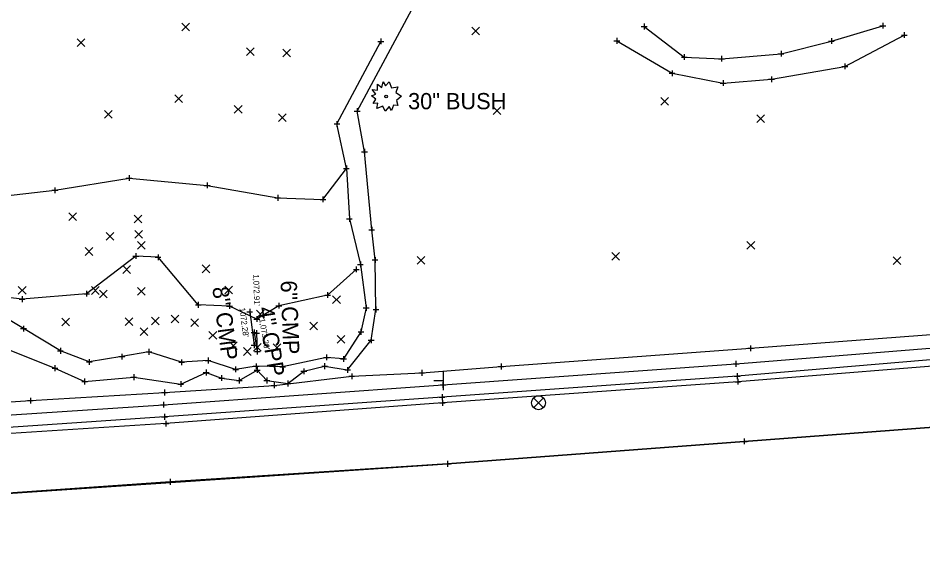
# Model space of a CAD drawing. Extents: x 203564 to 204038, y 344976 to 345157.
# Drawn here: x 203796.6 to 203952.6, y 344976.5 to 345067.2 of the extents above; entities that cross this region are included whole.
import ezdxf

# ---------------------------------------------------------------- set-up
doc = ezdxf.new("R2010")
doc.units = 0
for name, color, linetype in [('_CIVIL_CONSTRUCTION', 7, 'Continuous'), ('BM_P_Point', 7, 'Continuous'), ('DR_X_Storm_Sewer', 7, 'Continuous'), ('DR_X_Text', 7, 'Continuous'), ('PM_X_Channelizing_Line', 7, 'Continuous'), ('RW_X_CL', 7, 'Continuous'), ('RW_X_CL_100_Bearings', 7, 'Continuous'), ('RW_X_CL_100_Cardinal_Points', 7, 'Continuous'), ('RW_X_CL_100_Curve_Data', 7, 'Continuous'), ('RW_X_CL_100_Distances', 7, 'Continuous'), ('RW_X_CL_100_Stations', 7, 'Continuous'), ('RW_X_Esmt_LA', 7, 'Continuous'), ('SC_Scratch1', 7, 'Continuous'), ('SV_P_Control_Cells_Set', 7, 'Continuous'), ('SV_X_Break_Lines', 7, 'Continuous'), ('SV_X_Edge_of_Slip', 7, 'Continuous'), ('SV_X_Terrain_Boundary', 7, 'Continuous'), ('VG_X_Text', 7, 'Continuous')]:
    doc.layers.add(name, color=color, linetype=linetype)

msp = doc.modelspace()

# ---------------------------------------------------------------- linework, layer by layer
at = {"layer": '_CIVIL_CONSTRUCTION'}
for p, q in [((203904.05, 345065.76), (203905.05, 345065.76)), ((203904.55, 345066.26), (203904.55, 345065.26)), ((203904.55, 345065.76), (203904.55, 345065.76)), ((203945.2, 345065.9), (203946.2, 345065.9)), ((203945.7, 345066.4), (203945.7, 345065.4)), ((203945.7, 345065.9), (203945.7, 345065.9)), ((203859.15, 345063.7), (203859.15, 345062.7)), ((203899.85, 345063.78), (203899.85, 345062.78)), ((203936.83, 345063.76), (203936.83, 345062.76)), ((203948.91, 345064.29), (203949.91, 345064.29)), ((203949.41, 345064.79), (203949.41, 345063.79)), ((203949.41, 345064.29), (203949.41, 345064.29)), ((203858.65, 345063.2), (203859.65, 345063.2)), ((203859.15, 345063.2), (203859.15, 345063.2)), ((203899.35, 345063.28), (203900.35, 345063.28)), ((203899.85, 345063.28), (203899.85, 345063.28)), ((203936.33, 345063.26), (203937.33, 345063.26)), ((203936.83, 345063.26), (203936.83, 345063.26)), ((203910.97, 345060.49), (203911.97, 345060.49)), ((203911.47, 345060.99), (203911.47, 345059.99)), ((203911.47, 345060.49), (203911.47, 345060.49)), ((203917.39, 345060.2), (203918.39, 345060.2)), ((203917.89, 345060.7), (203917.89, 345059.7)), ((203917.89, 345060.2), (203917.89, 345060.2)), ((203927.65, 345061.07), (203928.65, 345061.07)), ((203928.15, 345061.57), (203928.15, 345060.57)), ((203928.15, 345061.07), (203928.15, 345061.07)), ((203938.65, 345058.89), (203939.65, 345058.89)), ((203939.15, 345059.39), (203939.15, 345058.39)), ((203939.15, 345058.89), (203939.15, 345058.89)), ((203908.87, 345057.69), (203909.87, 345057.69)), ((203909.37, 345058.19), (203909.37, 345057.19)), ((203909.37, 345057.69), (203909.37, 345057.69)), ((203926.51, 345057.16), (203926.51, 345056.16)), ((203917.66, 345056.01), (203918.66, 345056.01)), ((203918.16, 345056.51), (203918.16, 345055.51)), ((203918.16, 345056.01), (203918.16, 345056.01)), ((203926.01, 345056.66), (203927.01, 345056.66)), ((203926.51, 345056.66), (203926.51, 345056.66)), ((203854.59, 345051.18), (203855.59, 345051.18)), ((203855.09, 345051.68), (203855.09, 345050.68)), ((203855.09, 345051.18), (203855.09, 345051.18)), ((203851.59, 345049.45), (203851.59, 345048.45)), ((203851.09, 345048.95), (203852.09, 345048.95)), ((203851.59, 345048.95), (203851.59, 345048.95)), ((203856.34, 345044.65), (203856.34, 345043.65)), ((203855.84, 345044.15), (203856.84, 345044.15)), ((203856.34, 345044.15), (203856.34, 345044.15)), ((203853.22, 345041.8), (203853.22, 345040.8)), ((203815.75, 345040.12), (203815.75, 345039.12)), ((203852.72, 345041.3), (203853.72, 345041.3)), ((203853.22, 345041.3), (203853.22, 345041.3)), ((203815.25, 345039.62), (203816.25, 345039.62)), ((203815.75, 345039.62), (203815.75, 345039.62)), ((203828.72, 345038.37), (203829.72, 345038.37)), ((203829.22, 345038.87), (203829.22, 345037.87)), ((203829.22, 345038.37), (203829.22, 345038.37)), ((203802.46, 345037.51), (203803.46, 345037.51)), ((203802.96, 345038.01), (203802.96, 345037.01)), ((203802.96, 345037.51), (203802.96, 345037.51)), ((203840.88, 345036.21), (203841.88, 345036.21)), ((203841.38, 345036.71), (203841.38, 345035.71)), ((203841.38, 345036.21), (203841.38, 345036.21)), ((203848.68, 345035.95), (203849.68, 345035.95)), ((203849.18, 345036.45), (203849.18, 345035.45)), ((203849.18, 345035.95), (203849.18, 345035.95)), ((203853.24, 345032.59), (203854.24, 345032.59)), ((203853.74, 345033.09), (203853.74, 345032.09)), ((203853.74, 345032.59), (203853.74, 345032.59)), ((203857.09, 345030.7), (203858.09, 345030.7)), ((203857.59, 345031.2), (203857.59, 345030.2)), ((203857.59, 345030.7), (203857.59, 345030.7)), ((203816.43, 345026.17), (203817.43, 345026.17)), ((203816.93, 345026.67), (203816.93, 345025.67)), ((203816.93, 345026.17), (203816.93, 345026.17)), ((203820.26, 345025.96), (203821.26, 345025.96)), ((203820.76, 345026.46), (203820.76, 345025.46)), ((203820.76, 345025.96), (203820.76, 345025.96)), ((203858.17, 345026.01), (203858.17, 345025.01)), ((203854.93, 345024.38), (203854.93, 345023.38)), ((203855.14, 345024.74), (203856.14, 345024.74)), ((203855.64, 345025.24), (203855.64, 345024.24)), ((203855.64, 345024.74), (203855.64, 345024.74)), ((203857.67, 345025.51), (203858.67, 345025.51)), ((203858.17, 345025.51), (203858.17, 345025.51)), ((203854.43, 345023.88), (203855.43, 345023.88)), ((203854.93, 345023.88), (203854.93, 345023.88)), ((203807.94, 345019.69), (203808.94, 345019.69)), ((203808.44, 345020.19), (203808.44, 345019.19)), ((203808.44, 345019.69), (203808.44, 345019.69)), ((203849.99, 345019.96), (203849.99, 345018.96)), ((203796.81, 345018.74), (203797.81, 345018.74)), ((203797.31, 345019.24), (203797.31, 345018.24)), ((203797.31, 345018.74), (203797.31, 345018.74)), ((203827.69, 345018.26), (203827.69, 345017.26)), ((203833.07, 345018.06), (203833.07, 345017.06)), ((203841.57, 345018.12), (203841.57, 345017.12)), ((203849.49, 345019.46), (203850.49, 345019.46)), ((203849.99, 345019.46), (203849.99, 345019.46)), ((203827.19, 345017.76), (203828.19, 345017.76)), ((203827.69, 345017.76), (203827.69, 345017.76)), ((203832.57, 345017.56), (203833.57, 345017.56)), ((203833.07, 345017.56), (203833.07, 345017.56)), ((203841.07, 345017.62), (203842.07, 345017.62)), ((203841.57, 345017.62), (203841.57, 345017.62)), ((203856.12, 345017.23), (203857.12, 345017.23)), ((203856.62, 345017.73), (203856.62, 345016.73)), ((203856.62, 345017.23), (203856.62, 345017.23)), ((203857.82, 345016.96), (203858.82, 345016.96)), ((203858.32, 345017.46), (203858.32, 345016.46)), ((203858.32, 345016.96), (203858.32, 345016.96)), ((203837.28, 345015.31), (203838.28, 345015.31)), ((203837.78, 345015.81), (203837.78, 345014.81)), ((203837.78, 345015.31), (203837.78, 345015.31)), ((203797.05, 345013.67), (203798.05, 345013.67)), ((203797.55, 345014.17), (203797.55, 345013.17)), ((203797.55, 345013.67), (203797.55, 345013.67)), ((203855.73, 345013.61), (203855.73, 345012.61)), ((203855.23, 345013.11), (203856.23, 345013.11)), ((203855.73, 345013.11), (203855.73, 345013.11)), ((203857.49, 345012.16), (203857.49, 345011.16)), ((203803.92, 345010.34), (203803.92, 345009.34)), ((203856.99, 345011.66), (203857.99, 345011.66)), ((203857.49, 345011.66), (203857.49, 345011.66)), ((203922.41, 345010.28), (203923.41, 345010.28)), ((203922.91, 345010.78), (203922.91, 345009.78)), ((203922.91, 345010.28), (203922.91, 345010.28)), ((203803.42, 345009.84), (203804.42, 345009.84)), ((203803.92, 345009.84), (203803.92, 345009.84)), ((203814, 345008.83), (203815, 345008.83)), ((203814.5, 345009.33), (203814.5, 345008.33)), ((203814.5, 345008.83), (203814.5, 345008.83)), ((203818.69, 345009.65), (203819.69, 345009.65)), ((203819.19, 345010.15), (203819.19, 345009.15)), ((203819.19, 345009.65), (203819.19, 345009.65)), ((203849.29, 345008.7), (203850.29, 345008.7)), ((203849.79, 345009.2), (203849.79, 345008.2)), ((203849.79, 345008.7), (203849.79, 345008.7)), ((203852.72, 345008.94), (203852.72, 345007.94)), ((203802.98, 345007.35), (203802.98, 345006.35)), ((203808.39, 345007.92), (203809.39, 345007.92)), ((203808.89, 345008.42), (203808.89, 345007.42)), ((203808.89, 345007.92), (203808.89, 345007.92)), ((203824.31, 345007.86), (203825.31, 345007.86)), ((203824.81, 345008.36), (203824.81, 345007.36)), ((203824.81, 345007.86), (203824.81, 345007.86)), ((203828.88, 345008.16), (203829.88, 345008.16)), ((203829.38, 345008.66), (203829.38, 345007.66)), ((203829.38, 345008.16), (203829.38, 345008.16)), ((203837.17, 345007.17), (203838.17, 345007.17)), ((203837.67, 345007.67), (203837.67, 345006.67)), ((203837.67, 345007.17), (203837.67, 345007.17)), ((203842.23, 345007.56), (203842.23, 345006.56)), ((203848.96, 345007.18), (203849.96, 345007.18)), ((203849.46, 345007.68), (203849.46, 345006.68)), ((203849.46, 345007.18), (203849.46, 345007.18)), ((203852.22, 345008.44), (203853.22, 345008.44)), ((203852.72, 345008.44), (203852.72, 345008.44)), ((203879.89, 345007.63), (203879.89, 345006.63)), ((203919.88, 345007.59), (203920.88, 345007.59)), ((203920.38, 345008.09), (203920.38, 345007.09)), ((203920.38, 345007.59), (203920.38, 345007.59)), ((203802.48, 345006.85), (203803.48, 345006.85)), ((203802.98, 345006.85), (203802.98, 345006.85)), ((203816.55, 345005.8), (203816.55, 345004.8)), ((203828.54, 345006.1), (203829.54, 345006.1)), ((203829.04, 345006.6), (203829.04, 345005.6)), ((203829.04, 345006.1), (203829.04, 345006.1)), ((203831.71, 345005.64), (203831.71, 345004.64)), ((203833.62, 345006.64), (203834.62, 345006.64)), ((203834.12, 345007.14), (203834.12, 345006.14)), ((203834.12, 345006.64), (203834.12, 345006.64)), ((203837.35, 345006.51), (203838.35, 345006.51)), ((203837.85, 345007.01), (203837.85, 345006.01)), ((203837.85, 345006.51), (203837.85, 345006.51)), ((203841.73, 345007.06), (203842.73, 345007.06)), ((203842.23, 345007.06), (203842.23, 345007.06)), ((203845.39, 345006.3), (203846.39, 345006.3)), ((203845.89, 345006.8), (203845.89, 345005.8)), ((203845.89, 345006.3), (203845.89, 345006.3)), ((203852.93, 345006.53), (203853.93, 345006.53)), ((203853.43, 345007.03), (203853.43, 345006.03)), ((203853.43, 345006.53), (203853.43, 345006.53)), ((203854.14, 345005.95), (203854.14, 345004.95)), ((203865.71, 345006.03), (203866.71, 345006.03)), ((203866.21, 345006.53), (203866.21, 345005.53)), ((203866.21, 345006.03), (203866.21, 345006.03)), ((203879.39, 345007.13), (203880.39, 345007.13)), ((203879.89, 345007.13), (203879.89, 345007.13)), ((203920.59, 345005.96), (203920.59, 345004.96)), ((203807.6, 345004.55), (203808.6, 345004.55)), ((203808.1, 345005.05), (203808.1, 345004.05)), ((203808.1, 345004.55), (203808.1, 345004.55)), ((203816.05, 345005.3), (203817.05, 345005.3)), ((203816.55, 345005.3), (203816.55, 345005.3)), ((203824.16, 345004.1), (203825.16, 345004.1)), ((203824.66, 345004.6), (203824.66, 345003.6)), ((203824.66, 345004.1), (203824.66, 345004.1)), ((203831.21, 345005.14), (203832.21, 345005.14)), ((203831.71, 345005.14), (203831.71, 345005.14)), ((203834.26, 345004.72), (203835.26, 345004.72)), ((203834.76, 345005.22), (203834.76, 345004.22)), ((203834.76, 345004.72), (203834.76, 345004.72)), ((203839, 345004.71), (203840, 345004.71)), ((203839.5, 345005.21), (203839.5, 345004.21)), ((203839.5, 345004.71), (203839.5, 345004.71)), ((203840.75, 345004.38), (203840.75, 345003.38)), ((203842.62, 345004.19), (203843.62, 345004.19)), ((203843.12, 345004.69), (203843.12, 345003.69)), ((203843.12, 345004.19), (203843.12, 345004.19)), ((203853.64, 345005.45), (203854.64, 345005.45)), ((203854.14, 345005.45), (203854.14, 345005.45)), ((203869.87, 345004.45), (203869.87, 345003.45)), ((203920.09, 345005.46), (203921.09, 345005.46)), ((203920.19, 345004.51), (203921.19, 345004.51)), ((203920.59, 345005.46), (203920.59, 345005.46)), ((203920.69, 345005.01), (203920.69, 345004.01)), ((203920.69, 345004.51), (203920.69, 345004.51)), ((203821.37, 345002.65), (203822.37, 345002.65)), ((203821.87, 345003.15), (203821.87, 345002.15)), ((203821.87, 345002.65), (203821.87, 345002.65)), ((203840.25, 345003.88), (203841.25, 345003.88)), ((203840.75, 345003.88), (203840.75, 345003.88)), ((203869.37, 345003.95), (203870.37, 345003.95)), ((203869.87, 345003.95), (203869.87, 345003.95)), ((203798.25, 345001.25), (203799.25, 345001.25)), ((203798.75, 345001.75), (203798.75, 345000.75)), ((203798.75, 345001.25), (203798.75, 345001.25)), ((203821.68, 345001.04), (203821.68, 345000.04)), ((203869.22, 345001.85), (203870.22, 345001.85)), ((203869.72, 345002.35), (203869.72, 345001.35)), ((203869.72, 345001.85), (203869.72, 345001.85)), ((203869.77, 345001.34), (203869.77, 345000.34)), ((203821.18, 345000.54), (203822.18, 345000.54)), ((203821.68, 345000.54), (203821.68, 345000.54)), ((203869.27, 345000.84), (203870.27, 345000.84)), ((203869.77, 345000.84), (203869.77, 345000.84)), ((203821.37, 344998.44), (203822.37, 344998.44)), ((203821.87, 344998.94), (203821.87, 344997.94)), ((203821.87, 344998.44), (203821.87, 344998.44)), ((203821.61, 344997.28), (203822.61, 344997.28)), ((203822.11, 344997.78), (203822.11, 344996.78)), ((203822.11, 344997.28), (203822.11, 344997.28)), ((203921.82, 344994.71), (203921.82, 344993.71)), ((203921.82, 344994.71), (203921.82, 344993.71)), ((203921.32, 344994.21), (203922.32, 344994.21)), ((203921.32, 344994.21), (203922.32, 344994.21)), ((203921.82, 344994.21), (203921.82, 344994.21)), ((203921.82, 344994.21), (203921.82, 344994.21)), ((203870.16, 344990.35), (203871.16, 344990.35)), ((203870.16, 344990.35), (203871.16, 344990.35)), ((203870.66, 344990.85), (203870.66, 344989.85)), ((203870.66, 344990.85), (203870.66, 344989.85)), ((203870.66, 344990.35), (203870.66, 344990.35)), ((203870.66, 344990.35), (203870.66, 344990.35)), ((203822.32, 344987.23), (203823.32, 344987.23)), ((203822.32, 344987.23), (203823.32, 344987.23)), ((203822.82, 344987.73), (203822.82, 344986.73)), ((203822.82, 344987.73), (203822.82, 344986.73)), ((203822.82, 344987.23), (203822.82, 344987.23)), ((203822.82, 344987.23), (203822.82, 344987.23))]:
    msp.add_line(p, q, dxfattribs=at)
at = {"layer": 'BM_P_Point'}
for p, q in [((203887.18, 345000.03), (203885.49, 345001.73)), ((203885.49, 345000.03), (203887.18, 345001.73))]:
    msp.add_line(p, q, dxfattribs=at)
msp.add_circle((203886.33, 345000.88), 1.2, dxfattribs=at)
at = {"layer": 'DR_X_Storm_Sewer'}
for p, q in [((203836.55, 345016.57), (203837.3, 345010.82)), ((203837.33, 345012.99), (203837.86, 345009.7)), ((203837.74, 345012.9), (203837.86, 345009.7))]:
    msp.add_line(p, q, dxfattribs=at)
at = {"layer": 'PM_X_Channelizing_Line'}
msp.add_lwpolyline([(203965.84, 344997.53), (203921.82, 344994.21), (203870.66, 344990.35), (203822.82, 344987.23), (203774.29, 344983.85), (203725.72, 344980.7), (203661.3, 344976.54)], dxfattribs=at)
at = {"layer": 'RW_X_CL'}
for p, q in [((203869.91, 345006.24), (203869.91, 345003.04)), ((203869.91, 345004.64), (203868.31, 345004.64)), ((203869.91, 345004.64), (203869.91, 345004.64))]:
    msp.add_line(p, q, dxfattribs=at)
at = {"layer": 'RW_X_CL_100_Bearings'}
for p, q in [((203824.84, 345065.01), (203826.17, 345066.35)), ((203824.84, 345066.35), (203826.17, 345065.01)), ((203874.85, 345064.3), (203876.18, 345065.63)), ((203874.85, 345065.63), (203876.18, 345064.3)), ((203806.82, 345062.3), (203808.15, 345063.63)), ((203806.82, 345063.63), (203808.15, 345062.3)), ((203835.98, 345060.77), (203837.31, 345062.11)), ((203835.98, 345062.11), (203837.31, 345060.77)), ((203842.25, 345060.54), (203843.58, 345061.88)), ((203842.25, 345061.88), (203843.58, 345060.54)), ((203823.62, 345052.63), (203824.95, 345053.97)), ((203823.62, 345053.97), (203824.95, 345052.63)), ((203907.44, 345052.2), (203908.77, 345053.54)), ((203907.44, 345053.54), (203908.77, 345052.2)), ((203811.51, 345049.93), (203812.85, 345051.26)), ((203811.51, 345051.26), (203812.85, 345049.93)), ((203833.9, 345050.79), (203835.23, 345052.13)), ((203833.9, 345052.13), (203835.23, 345050.79)), ((203878.51, 345050.58), (203879.85, 345051.92)), ((203878.51, 345051.92), (203879.85, 345050.58)), ((203841.52, 345049.37), (203842.85, 345050.7)), ((203841.52, 345050.7), (203842.85, 345049.37)), ((203923.99, 345049.19), (203925.33, 345050.53)), ((203923.99, 345050.53), (203925.33, 345049.19)), ((203805.35, 345032.28), (203806.68, 345033.61)), ((203805.35, 345033.61), (203806.68, 345032.28)), ((203816.62, 345031.91), (203817.96, 345033.25)), ((203816.62, 345033.25), (203817.96, 345031.91)), ((203816.73, 345029.27), (203818.06, 345030.6)), ((203816.73, 345030.6), (203818.06, 345029.27)), ((203811.8, 345028.9), (203813.13, 345030.23)), ((203811.8, 345030.23), (203813.13, 345028.9)), ((203808.18, 345026.29), (203809.51, 345027.63)), ((203808.18, 345027.63), (203809.51, 345026.29)), ((203817.19, 345027.36), (203818.52, 345028.7)), ((203817.19, 345028.7), (203818.52, 345027.36)), ((203922.28, 345027.36), (203923.61, 345028.7)), ((203922.28, 345028.7), (203923.61, 345027.36)), ((203865.43, 345024.78), (203866.77, 345026.12)), ((203865.43, 345026.12), (203866.77, 345024.78)), ((203898.99, 345025.45), (203900.32, 345026.78)), ((203898.99, 345026.78), (203900.32, 345025.45)), ((203947.5, 345024.72), (203948.83, 345026.06)), ((203947.5, 345026.06), (203948.83, 345024.72)), ((203814.7, 345023.18), (203816.03, 345024.52)), ((203814.7, 345024.52), (203816.03, 345023.18)), ((203828.34, 345023.3), (203829.67, 345024.64)), ((203828.34, 345024.64), (203829.67, 345023.3)), ((203796.65, 345019.59), (203797.99, 345020.93)), ((203796.65, 345020.93), (203797.99, 345019.59)), ((203809.25, 345019.56), (203810.58, 345020.9)), ((203809.25, 345020.9), (203810.58, 345019.56)), ((203810.64, 345018.97), (203811.97, 345020.3)), ((203810.64, 345020.3), (203811.97, 345018.97)), ((203817.2, 345019.44), (203818.53, 345020.78)), ((203817.2, 345020.78), (203818.53, 345019.44)), ((203832.27, 345019.64), (203833.6, 345020.98)), ((203832.27, 345020.98), (203833.6, 345019.64)), ((203850.84, 345017.99), (203852.18, 345019.33)), ((203850.84, 345019.33), (203852.18, 345017.99)), ((203837.73, 345015.49), (203839.06, 345016.83)), ((203837.73, 345016.83), (203839.06, 345015.49)), ((203804.15, 345014.15), (203805.49, 345015.49)), ((203804.15, 345015.49), (203805.49, 345014.15)), ((203815.06, 345014.2), (203816.39, 345015.54)), ((203815.06, 345015.54), (203816.39, 345014.2)), ((203819.64, 345014.31), (203820.97, 345015.65)), ((203819.64, 345015.65), (203820.97, 345014.31)), ((203823.02, 345014.67), (203824.36, 345016.01)), ((203823.02, 345016.01), (203824.36, 345014.67)), ((203826.41, 345014.03), (203827.74, 345015.36)), ((203826.41, 345015.36), (203827.74, 345014.03)), ((203817.66, 345012.46), (203819, 345013.8)), ((203817.66, 345013.8), (203819, 345012.46)), ((203846.9, 345013.46), (203848.24, 345014.79)), ((203846.9, 345014.79), (203848.24, 345013.46)), ((203829.53, 345011.82), (203830.86, 345013.15)), ((203829.53, 345013.15), (203830.86, 345011.82)), ((203851.63, 345011.17), (203852.96, 345012.5)), ((203851.63, 345012.5), (203852.96, 345011.17)), ((203833.05, 345010.07), (203834.38, 345011.41)), ((203833.05, 345011.41), (203834.38, 345010.07)), ((203835.49, 345009.05), (203836.82, 345010.38)), ((203835.49, 345010.38), (203836.82, 345009.05)), ((203837.19, 345009.75), (203838.52, 345011.08)), ((203837.19, 345011.08), (203838.52, 345009.75)), ((203840.6, 345009.72), (203841.93, 345011.06)), ((203840.6, 345011.06), (203841.93, 345009.72))]:
    msp.add_line(p, q, dxfattribs=at)
at = {"layer": 'RW_X_CL_100_Cardinal_Points'}
msp.add_lwpolyline([(203859.98, 345055.51), (203860.58, 345056.24), (203861, 345055.19), (203862.09, 345055.37), (203861.75, 345054.36), (203862.7, 345053.76), (203861.84, 345053.03), (203862.09, 345052.12), (203861.34, 345052.18), (203861.01, 345051.27), (203860.58, 345051.96), (203859.91, 345051.15), (203859.48, 345052.03), (203858.46, 345051.6), (203858.65, 345052.54), (203857.84, 345052.46), (203858.31, 345053.25), (203857.54, 345053.82), (203858.28, 345054.08), (203857.67, 345054.89), (203858.61, 345054.78), (203858.58, 345055.81), (203859.33, 345055.25), (203859.54, 345056.23), (203859.98, 345055.51)], dxfattribs=at)
msp.add_circle((203860.06, 345053.7), 0.23, dxfattribs=at)
at = {"layer": 'RW_X_CL_100_Curve_Data'}
for p, q in [((203836.05, 345016.57), (203837.05, 345016.57)), ((203836.55, 345017.07), (203836.55, 345016.07)), ((203836.55, 345016.57), (203836.55, 345016.57)), ((203837.33, 345013.49), (203837.33, 345012.49)), ((203837.74, 345013.4), (203837.74, 345012.4)), ((203836.83, 345012.99), (203837.83, 345012.99)), ((203837.24, 345012.9), (203838.24, 345012.9)), ((203837.33, 345012.99), (203837.33, 345012.99)), ((203837.74, 345012.9), (203837.74, 345012.9)), ((203836.8, 345010.82), (203837.8, 345010.82)), ((203837.3, 345011.32), (203837.3, 345010.32)), ((203837.3, 345010.82), (203837.3, 345010.82)), ((203837.36, 345009.7), (203838.36, 345009.7)), ((203837.86, 345010.2), (203837.86, 345009.2)), ((203837.86, 345009.7), (203837.86, 345009.7))]:
    msp.add_line(p, q, dxfattribs=at)
at = {"layer": 'RW_X_CL_100_Distances'}
msp.add_lwpolyline([(203964.79, 345009.21), (203920.59, 345005.46), (203869.72, 345001.85), (203821.87, 344998.44), (203773.9, 344995.18), (203724.14, 344991.94), (203661.21, 344987.77)], dxfattribs=at)
at = {"layer": 'RW_X_CL_100_Stations'}
msp.add_lwpolyline([(203660.93, 344989.96), (203723.73, 344994.26), (203773.58, 344997.37), (203821.68, 345000.54), (203869.87, 345003.95), (203920.38, 345007.59), (203965.26, 345011.21)], dxfattribs=at)
at = {"layer": 'RW_X_Esmt_LA'}
msp.add_lwpolyline([(203965.84, 344997.53), (203921.82, 344994.21), (203870.66, 344990.35), (203822.82, 344987.23), (203774.29, 344983.85), (203725.72, 344980.7), (203661.3, 344976.54)], dxfattribs=at)
at = {"layer": 'SV_P_Control_Cells_Set'}
msp.add_lwpolyline([(203965, 345008.04), (203920.69, 345004.51), (203869.77, 345000.84), (203822.11, 344997.28), (203773.93, 344994.18), (203724.2, 344990.95), (203660.85, 344986.88)], dxfattribs=at)
at = {"layer": 'SV_X_Break_Lines'}
for points in [[(203765.03, 345042.4), (203770.99, 345038.95), (203777.79, 345035.43), (203787.39, 345035.74), (203802.96, 345037.51), (203815.75, 345039.62), (203829.22, 345038.37), (203841.38, 345036.21), (203849.18, 345035.95), (203853.22, 345041.3), (203851.59, 345048.95), (203859.15, 345063.2)], [(203853.22, 345041.3), (203853.74, 345032.59), (203855.64, 345024.74), (203856.62, 345017.23), (203855.73, 345013.11), (203852.72, 345008.44), (203849.79, 345008.7), (203842.23, 345007.06), (203837.67, 345007.17), (203834.12, 345006.64), (203829.38, 345008.16), (203824.81, 345007.86), (203819.19, 345009.65), (203814.5, 345008.83), (203808.89, 345007.92), (203803.92, 345009.84), (203797.55, 345013.67), (203790.31, 345017.97)], [(203854.93, 345023.88), (203849.99, 345019.46), (203841.57, 345017.62), (203837.78, 345015.31), (203833.07, 345017.56), (203827.69, 345017.76), (203820.76, 345025.96), (203816.93, 345026.17), (203808.44, 345019.69), (203797.31, 345018.74), (203790.36, 345019.57)], [(203661.18, 344992.05), (203683.55, 344993.04), (203711.97, 344996.72), (203761.48, 344999.07), (203779.57, 345000.01), (203798.75, 345001.25), (203821.87, 345002.65), (203840.75, 345003.88), (203854.14, 345005.45), (203866.21, 345006.03), (203879.89, 345007.13), (203922.91, 345010.28), (203960.08, 345013.12)]]:
    msp.add_lwpolyline(points, dxfattribs=at)
at = {"layer": 'SV_X_Edge_of_Slip'}
for points in [[(203795.1, 345010.01), (203802.98, 345006.85), (203808.1, 345004.55), (203816.55, 345005.3), (203824.66, 345004.1), (203829.04, 345006.1), (203831.71, 345005.14), (203834.76, 345004.72), (203837.85, 345006.51), (203839.5, 345004.71), (203843.12, 345004.19), (203845.89, 345006.3), (203849.46, 345007.18), (203853.43, 345006.53), (203857.49, 345011.66), (203858.32, 345016.96), (203858.17, 345025.51), (203857.59, 345030.7), (203856.34, 345044.15), (203855.09, 345051.18), (203865.29, 345070.2)], [(203904.55, 345065.76), (203911.47, 345060.49), (203917.89, 345060.2), (203928.15, 345061.07), (203936.83, 345063.26), (203945.7, 345065.9)], [(203899.85, 345063.28), (203909.37, 345057.69), (203918.16, 345056.01), (203926.51, 345056.66), (203939.15, 345058.89), (203949.41, 345064.29)]]:
    msp.add_lwpolyline(points, dxfattribs=at)
at = {"layer": 'SV_X_Terrain_Boundary'}
msp.add_lwpolyline([(203688.25, 345107.3), (203663.45, 345073.36), (203661.3, 344976.54), (203725.72, 344980.7), (203774.29, 344983.85), (203870.66, 344990.35), (203921.82, 344994.21), (203965.84, 344997.53), (203960.08, 345013.12), (203981.66, 345100.71), (203974.83, 345120.91), (203950.66, 345136.61), (203932.67, 345155.23), (203932.67, 345155.29), (203859.66, 345150.34), (203831.78, 345149.07), (203795.84, 345146.71), (203756.25, 345143.96), (203689.69, 345139.7)], close=True, dxfattribs=at)

# ---------------------------------------------------------------- texts
at = {"layer": 'DR_X_Text'}
for s, rotation, p in [('6" CMP', 272.1417, (203841.87, 345021.92)), ('8" CMP', 277.3979, (203830.1, 345020.75)), ('4" CPP', 279.1748, (203837.93, 345017.24))]:
    msp.add_text(s, height=2.8, rotation=rotation, dxfattribs=at).set_placement(p)
at = {"layer": 'SC_Scratch1'}
for s, rotation, p in [("1,072.91'", 272.1417, (203837.14, 345023.01)), ("1072.28'", 277.3979, (203834.78, 345017.19)), ("1,073.20'", 279.1748, (203838.19, 345015.33))]:
    msp.add_text(s, height=1, rotation=rotation, dxfattribs=at).set_placement(p)
at = {"layer": 'VG_X_Text'}
msp.add_text('30" BUSH', height=2.8, dxfattribs=at).set_placement((203863.86, 345051.49))

doc.saveas('drawing.dxf')
